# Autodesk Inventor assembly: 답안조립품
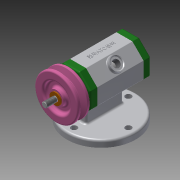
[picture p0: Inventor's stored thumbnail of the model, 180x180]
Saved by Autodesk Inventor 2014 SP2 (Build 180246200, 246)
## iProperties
Created: 2021-02
Part Number: 답안조립품
Document SubType Name: Assembly
Designer: 거성
Author: 거성
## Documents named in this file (11)
- C:\Users\거성\Desktop\710204V1005\답안조립품.iam
- C:\Users\거성\Desktop\710204V1005\본체.ipt
- C:\Users\거성\Desktop\710204V1005\베어링 15 x 32 x 9.ipt
- C:\Users\거성\Desktop\710204V1005\뒤커버.ipt
- C:\Users\거성\Desktop\710204V1005\앞커버.ipt
- C:\Users\거성\Desktop\710204V1005\오일 실 15 25 7.ipt
- C:\Users\거성\Desktop\710204V1005\볼트 M4 x 12.ipt
- C:\Users\거성\Desktop\710204V1005\축.ipt
- C:\Users\거성\Desktop\710204V1005\키 3 x 3 x 12.ipt
- C:\Users\거성\Desktop\710204V1005\V벨트풀리.ipt
- C:\Users\거성\Desktop\710204V1005\와셔 8x17.ipt
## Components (1 placed, 1 different names)
1. V벨트풀리:1
